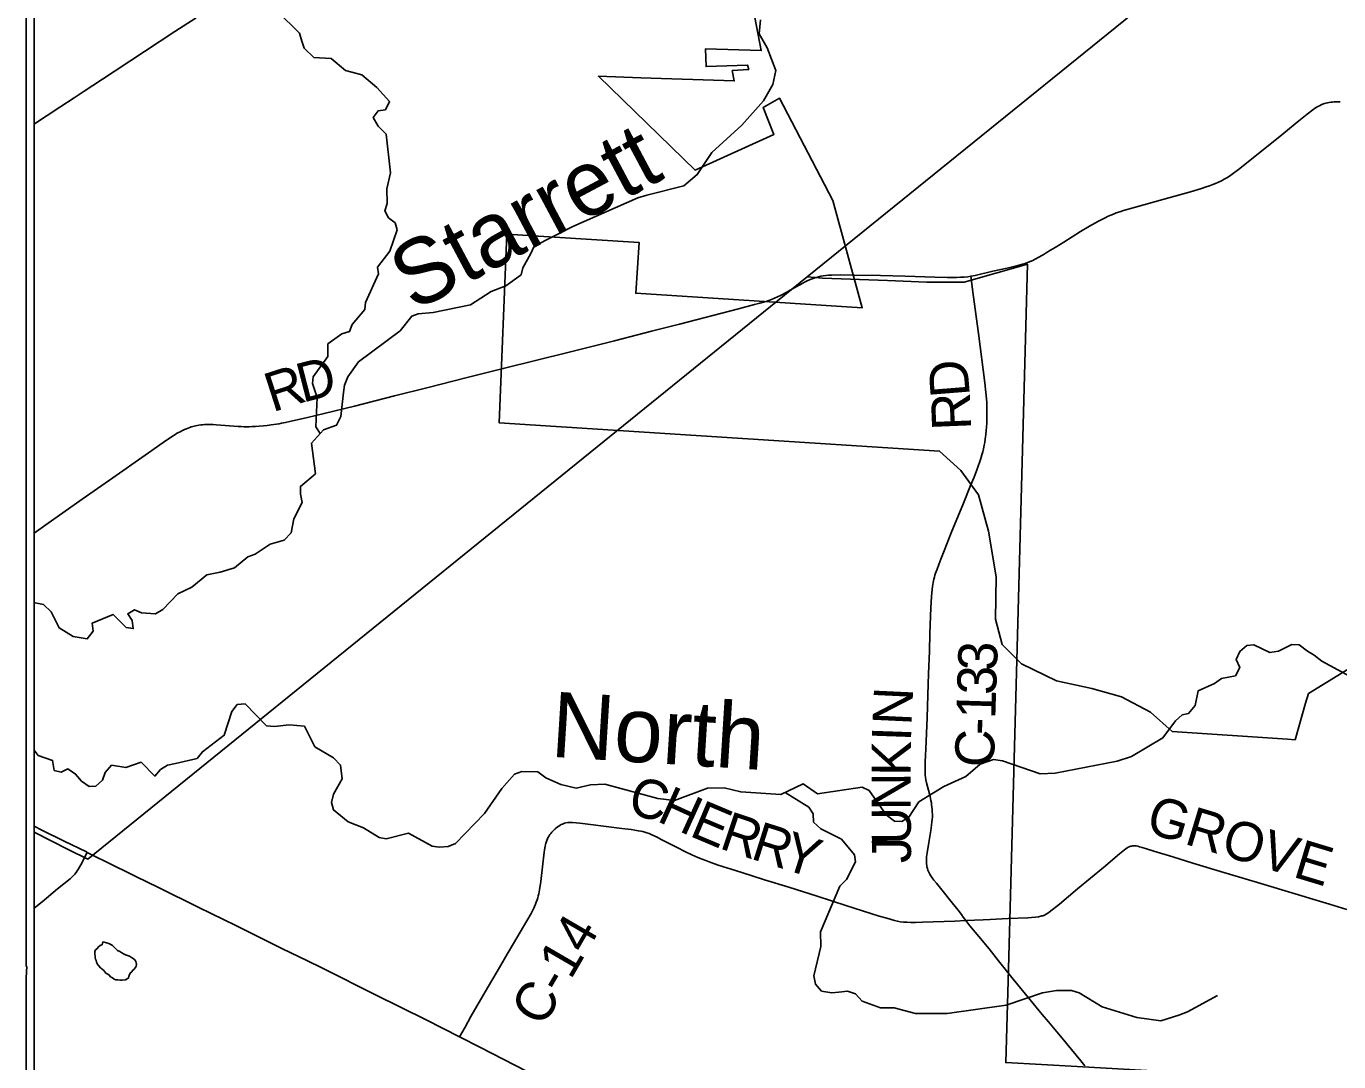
# Model space of a CAD drawing. Extents: x -5.4 to 49.9, y 13.2 to 48.4.
# Drawn here: x 26.266 to 28.171, y 44.845 to 46.348 of the extents above; entities that cross this region are included whole.
import ezdxf

# ---------------------------------------------------------------- set-up
doc = ezdxf.new("R2010")
doc.units = 0
for name, color, linetype in [('GM_X_Corporation', 7, 'Continuous'), ('GM_X_County_Road', 7, 'Continuous'), ('GM_X_County_Road_Text', 7, 'Continuous'), ('GM_X_Minor_Lake', 7, 'Continuous'), ('GM_X_Minor_River', 7, 'Continuous'), ('GM_X_Minor_River_Text', 7, 'Continuous'), ('GM_X_Township', 7, 'Continuous'), ('GM_X_Township_Road', 7, 'Continuous')]:
    doc.layers.add(name, color=color, linetype=linetype)

msp = doc.modelspace()

# ---------------------------------------------------------------- linework, layer by layer
at = {"layer": 'GM_X_Corporation'}
for p, q in [((26.2655, 46.6728), (26.2655, 44.9832)), ((26.2655, 44.9666), (26.2655, 44.8206))]:
    msp.add_line(p, q, dxfattribs=at)
for points in [[(28.3968, 45.5449), (28.1271, 45.3795), (28.123, 45.3654), (28.1079, 45.3123), (28.0969, 45.313), (27.9295, 45.3243), (27.898, 45.3524), (27.8556, 45.3746), (27.8126, 45.387), (27.7613, 45.3977), (27.7105, 45.4224), (27.6823, 45.4505), (27.6728, 45.4873), (27.674, 45.5489), (27.6626, 45.6154), (27.6481, 45.6682), (27.6227, 45.7031), (27.5916, 45.7316), (26.9521, 45.7726), (26.9634, 46.0466), (27.1552, 46.0345), (27.1505, 45.9606), (27.4794, 45.9397), (27.4366, 46.0951), (27.359, 46.2441), (27.3354, 46.2306), (27.3511, 46.191), (27.2369, 46.1395), (27.0962, 46.2758), (27.158, 46.2736), (27.2935, 46.2689), (27.2906, 46.284), (27.3145, 46.2856), (27.3129, 46.2919), (27.2526, 46.2898), (27.2517, 46.3155), (27.3326, 46.3129), (27.321, 46.3737)], [(26.2655, 44.9832), (26.2665, 44.9831), (26.2655, 44.9666)]]:
    msp.add_lwpolyline(points, dxfattribs=at)
at = {"layer": 'GM_X_County_Road'}
for points in [[(27.7269, 46.0083), (27.7294, 46.0095), (27.7316, 46.0107), (27.7336, 46.0119), (27.7418, 46.0164), (27.7466, 46.0192), (27.7529, 46.023), (27.7594, 46.027), (27.772, 46.0349), (27.7961, 46.0501), (27.8094, 46.0581), (27.8224, 46.0654), (27.8318, 46.0702), (27.8354, 46.0719), (27.8402, 46.074), (27.844, 46.0756), (27.8482, 46.0772), (27.8531, 46.0788), (27.8588, 46.0807), (27.8761, 46.0857), (27.9156, 46.0968), (27.9557, 46.108), (27.9718, 46.1128), (27.9787, 46.115), (27.9836, 46.1167), (27.9884, 46.1184), (27.9924, 46.1201), (27.9968, 46.122), (28.0009, 46.124), (28.005, 46.1261), (28.0086, 46.1283), (28.0126, 46.1309), (28.0164, 46.1335), (28.0254, 46.1402), (28.0831, 46.1864), (28.113, 46.2108), (28.1251, 46.2205), (28.1335, 46.2269), (28.136, 46.2287), (28.1386, 46.2303), (28.1408, 46.2317), (28.1434, 46.233), (28.1459, 46.2342), (28.1478, 46.235), (28.1503, 46.236), (28.1528, 46.2367), (28.1547, 46.2372), (28.1572, 46.2377), (28.1596, 46.238), (28.162, 46.2383), (28.1644, 46.2384), (28.1669, 46.2385), (28.1699, 46.2385), (28.1731, 46.2384)], [(27.6368, 45.9853), (27.6433, 45.9866), (27.6691, 45.9925), (27.6896, 45.9971), (27.6993, 45.9994), (27.7053, 46.0009), (27.7118, 46.0028), (27.7158, 46.0041), (27.7191, 46.0052), (27.7221, 46.0063), (27.7256, 46.0077), (27.7269, 46.0083)], [(27.3746, 45.965), (27.3783, 45.9671), (27.3929, 45.9753), (27.3964, 45.9771), (27.3996, 45.9787), (27.4026, 45.9801), (27.4054, 45.9812), (27.4083, 45.9823), (27.4119, 45.9835), (27.4157, 45.9845), (27.4192, 45.9853), (27.4228, 45.9859), (27.4267, 45.9864), (27.4303, 45.9868), (27.4334, 45.987)], [(27.4334, 45.987), (27.4348, 45.9871), (27.4472, 45.9874), (27.4678, 45.9871), (27.5057, 45.9862), (27.5417, 45.9854), (27.5845, 45.984), (27.6032, 45.9835), (27.61, 45.9834), (27.6164, 45.9835), (27.622, 45.9838), (27.6273, 45.9841), (27.6324, 45.9847), (27.6368, 45.9853)], [(27.6295, 45.0497), (27.6261, 45.0547), (27.6233, 45.0586), (27.6184, 45.0647), (27.6098, 45.0755), (27.5948, 45.0945), (27.587, 45.1043), (27.5835, 45.1086), (27.582, 45.1106), (27.5791, 45.1147), (27.5776, 45.1172), (27.5764, 45.1192), (27.5754, 45.1213), (27.5747, 45.1232), (27.5739, 45.1255), (27.5733, 45.1277), (27.573, 45.1299), (27.5726, 45.1324), (27.5725, 45.1349), (27.5725, 45.1375), (27.5726, 45.1399), (27.5728, 45.1422), (27.5736, 45.1483), (27.576, 45.163), (27.577, 45.1691), (27.579, 45.1807), (27.5801, 45.1885), (27.5806, 45.1932), (27.5809, 45.1968), (27.5811, 45.2002), (27.5811, 45.2036), (27.581, 45.2076), (27.5809, 45.211), (27.5805, 45.2147), (27.5801, 45.2178), (27.5797, 45.221), (27.5791, 45.224), (27.5785, 45.2272), (27.5778, 45.23), (27.5754, 45.2391), (27.5727, 45.2499), (27.5718, 45.254), (27.5711, 45.2578), (27.5708, 45.2611), (27.5705, 45.2641), (27.5705, 45.2705), (27.5708, 45.2802), (27.5711, 45.2895), (27.5715, 45.2994), (27.5734, 45.3441), (27.5747, 45.3777), (27.5756, 45.4081), (27.5769, 45.441), (27.5777, 45.4665), (27.5791, 45.5037), (27.5801, 45.5205), (27.5809, 45.5306), (27.5814, 45.5348), (27.5818, 45.5378), (27.5823, 45.5405), (27.5828, 45.543), (27.5833, 45.5454), (27.5841, 45.5482), (27.5849, 45.5511), (27.5859, 45.5542), (27.5879, 45.56), (27.5903, 45.5669), (27.5932, 45.5746), (27.5981, 45.5867), (27.6086, 45.6126), (27.6263, 45.6558), (27.6367, 45.6815), (27.6417, 45.6938), (27.6453, 45.703), (27.6503, 45.7164), (27.6517, 45.7209), (27.6532, 45.7259), (27.6544, 45.7306), (27.6555, 45.7349), (27.6565, 45.7399), (27.6572, 45.7441), (27.658, 45.7495), (27.6588, 45.7552), (27.6594, 45.7616), (27.6598, 45.7663), (27.6601, 45.7719), (27.6602, 45.7769), (27.6604, 45.7845), (27.6604, 45.7924), (27.6603, 45.7976), (27.6601, 45.8023), (27.659, 45.8166), (27.6575, 45.8308), (27.6482, 45.9023), (27.6405, 45.959), (27.6368, 45.9853)], [(26.2771, 45.6125), (26.294, 45.6243), (26.3468, 45.6615), (26.3865, 45.6892), (26.4429, 45.729), (26.4643, 45.7439), (26.4777, 45.753), (26.4812, 45.7552), (26.4837, 45.7568), (26.4867, 45.7585), (26.4889, 45.7596), (26.4912, 45.7609), (26.4934, 45.7619), (26.4954, 45.7629), (26.4981, 45.764), (26.5004, 45.7649), (26.5028, 45.7657), (26.5052, 45.7665), (26.5073, 45.7671), (26.5094, 45.7677), (26.5114, 45.7682), (26.5137, 45.7687), (26.5162, 45.7691), (26.5191, 45.7695), (26.5214, 45.7698), (26.5243, 45.77), (26.528, 45.7702), (26.5326, 45.7701), (26.5368, 45.77), (26.5413, 45.7698), (26.5542, 45.7688), (26.5734, 45.7672), (26.5774, 45.767), (26.5817, 45.7668), (26.5852, 45.7668), (26.589, 45.7668), (26.5934, 45.767), (26.5983, 45.7673), (26.6036, 45.7676), (26.6098, 45.7682), (26.6152, 45.7687), (26.6209, 45.7694), (26.6248, 45.7699), (26.6289, 45.7705), (26.6326, 45.7711), (26.6362, 45.7718), (26.6419, 45.7729), (26.6501, 45.7747), (26.6737, 45.7801), (26.6979, 45.7859), (26.7419, 45.7969), (26.8003, 45.8116), (26.8473, 45.8235), (26.9058, 45.8382), (26.9582, 45.8512), (27.054, 45.8752), (27.1197, 45.8917), (27.1733, 45.9054), (27.2142, 45.916), (27.2996, 45.938), (27.3231, 45.9441), (27.3304, 45.9461), (27.3362, 45.9478), (27.3397, 45.9489), (27.3435, 45.9502), (27.3474, 45.9516), (27.3517, 45.9534), (27.3561, 45.9553), (27.3608, 45.9575), (27.3696, 45.9622), (27.3746, 45.965)], [(26.2771, 45.1867), (26.2882, 45.1813), (26.3205, 45.1653), (26.3529, 45.1494), (26.354, 45.1488)], [(26.8947, 44.8808), (26.9027, 44.8952), (26.9112, 44.9104), (26.932, 44.9464), (26.9527, 44.9818), (26.9639, 45.0011), (26.9731, 45.0167), (26.9922, 45.0492), (26.9984, 45.0602), (27.0024, 45.0679), (27.0036, 45.0704), (27.0049, 45.0736), (27.006, 45.0764), (27.0073, 45.08), (27.0082, 45.0829), (27.009, 45.0859), (27.0097, 45.0886), (27.0102, 45.0913), (27.0109, 45.0944), (27.0128, 45.1067), (27.0152, 45.1277), (27.0175, 45.1489), (27.018, 45.1521), (27.0184, 45.1552), (27.0189, 45.1578), (27.0195, 45.1599), (27.0201, 45.1622), (27.0209, 45.1645), (27.0216, 45.1663), (27.0224, 45.1684), (27.0234, 45.1707), (27.0246, 45.173), (27.0258, 45.1748), (27.027, 45.1764), (27.0285, 45.1781), (27.03, 45.1798), (27.0333, 45.1829), (27.0369, 45.1858), (27.0387, 45.187), (27.0405, 45.1882), (27.0422, 45.1891), (27.044, 45.1899), (27.0453, 45.1905), (27.0472, 45.1911), (27.0491, 45.1916), (27.0517, 45.1921), (27.0541, 45.1924), (27.0563, 45.1923), (27.0586, 45.1922), (27.0691, 45.1912), (27.0849, 45.1892), (27.1073, 45.1864), (27.1302, 45.1836), (27.1436, 45.1819), (27.1491, 45.1811), (27.154, 45.1803), (27.1577, 45.1796), (27.1608, 45.179), (27.1636, 45.1782), (27.1667, 45.1772), (27.17, 45.176), (27.1736, 45.1745), (27.1815, 45.1708), (27.1876, 45.1677), (27.2108, 45.1557), (27.2219, 45.15), (27.2319, 45.1452), (27.2404, 45.1414), (27.2468, 45.1388), (27.252, 45.1368), (27.2572, 45.1349), (27.2702, 45.1304), (27.2891, 45.1243), (27.3045, 45.1194), (27.3376, 45.109), (27.3725, 45.0982), (27.4141, 45.0851), (27.4555, 45.0718), (27.5041, 45.0563), (27.5148, 45.0531), (27.526, 45.05), (27.5304, 45.0489), (27.5345, 45.0482), (27.5392, 45.0476), (27.5444, 45.0473), (27.5498, 45.0471), (27.5568, 45.0471), (27.5666, 45.0474), (27.614, 45.049), (27.6295, 45.0497)], [(26.2771, 45.0678), (26.2885, 45.0772), (26.311, 45.0958), (26.3293, 45.1106), (26.3322, 45.1133), (26.3342, 45.1153), (26.3361, 45.1173), (26.3378, 45.1194), (26.3395, 45.1218), (26.3416, 45.125), (26.3468, 45.1341), (26.3522, 45.1452), (26.354, 45.1488)], [(26.354, 45.1488), (26.3676, 45.1421)], [(27.6652, 45.0513), (27.691, 45.0527), (27.7196, 45.0539), (27.7249, 45.0543), (27.7308, 45.0548), (27.7351, 45.0554), (27.7386, 45.0561), (27.7403, 45.0565), (27.7417, 45.0569), (27.7429, 45.0573), (27.7441, 45.0579), (27.7464, 45.0592), (27.7488, 45.0607), (27.7507, 45.0621), (27.7655, 45.0738), (27.7917, 45.0957), (27.8295, 45.127), (27.8527, 45.1468), (27.86, 45.1525), (27.8621, 45.1541), (27.8641, 45.1554), (27.8655, 45.1562), (27.8668, 45.1569), (27.868, 45.1574), (27.8691, 45.1578), (27.8702, 45.158), (27.8715, 45.1582), (27.8727, 45.1584), (27.874, 45.1584), (27.8754, 45.1583), (27.8771, 45.1581), (27.8794, 45.1577), (27.8819, 45.1571), (27.8858, 45.1561), (27.8921, 45.1542), (27.9028, 45.1508), (27.9301, 45.1423), (27.9592, 45.1334), (27.9996, 45.121), (28.0306, 45.1118), (28.0627, 45.1021), (28.143, 45.078), (28.1579, 45.0735), (28.1829, 45.0659)], [(26.3676, 45.1421), (26.3796, 45.1361), (26.4258, 45.1133), (26.4565, 45.0982), (26.5161, 45.0688), (26.5696, 45.0425), (26.6376, 45.009), (26.6728, 44.9919), (26.6957, 44.9806), (26.7728, 44.9419), (26.8462, 44.9055), (26.8947, 44.8808)], [(27.6295, 45.0497), (27.655, 45.0508), (27.6652, 45.0513)], [(26.8947, 44.8808), (26.925, 44.8655), (27.009, 44.8225), (27.0663, 44.7925), (27.196, 44.7242), (27.2235, 44.7097), (27.2445, 44.6989), (27.2809, 44.68), (27.3256, 44.6569), (27.3583, 44.6402), (27.4753, 44.5798), (27.506, 44.5634), (27.543, 44.544)]]:
    msp.add_lwpolyline(points, dxfattribs=at)
at = {"layer": 'GM_X_Minor_Lake'}
msp.add_lwpolyline([(26.3766, 45.0189), (26.3785, 45.0185), (26.3819, 45.0173), (26.3854, 45.0165), (26.3884, 45.015), (26.3906, 45.0134), (26.3933, 45.0111), (26.3959, 45.0084), (26.3981, 45.0065), (26.4012, 45.005), (26.4042, 45.003), (26.4076, 45.0011), (26.4095, 45.0003), (26.4125, 44.9992), (26.4155, 44.998), (26.4182, 44.9964), (26.4208, 44.9945), (26.4234, 44.9926), (26.4245, 44.9903), (26.4253, 44.9884), (26.4256, 44.9861), (26.4252, 44.9838), (26.4241, 44.9816), (26.4218, 44.9789), (26.4199, 44.9774), (26.4187, 44.9755), (26.4168, 44.974), (26.4152, 44.9714), (26.4144, 44.9687), (26.414, 44.9665), (26.4121, 44.965), (26.4095, 44.9638), (26.4049, 44.9631), (26.4026, 44.9632), (26.3985, 44.9636), (26.3954, 44.964), (26.3932, 44.9648), (26.3909, 44.9667), (26.3879, 44.9682), (26.386, 44.9706), (26.3841, 44.9721), (26.3811, 44.9736), (26.3781, 44.9771), (26.3759, 44.9794), (26.3732, 44.9813), (26.3706, 44.9844), (26.3683, 44.9871), (26.3676, 44.9897), (26.3669, 44.992), (26.3661, 44.9939), (26.3658, 44.9958), (26.3654, 44.9985), (26.3651, 45.0004), (26.3651, 45.0023), (26.3651, 45.005), (26.3659, 45.0072), (26.3682, 45.0087), (26.3713, 45.0125), (26.3739, 45.014), (26.3758, 45.0147), (26.3766, 45.0189)], dxfattribs=at)
at = {"layer": 'GM_X_Minor_River'}
for points in [[(26.6921, 45.7569), (26.6862, 45.7665), (26.688, 45.8093), (26.6811, 45.8296), (26.682, 45.8391), (26.7033, 45.8687), (26.7036, 45.887), (26.7239, 45.9019), (26.7349, 45.9051), (26.7385, 45.9153), (26.757, 45.9371), (26.758, 45.9473), (26.7772, 45.9888), (26.7754, 45.9987), (26.7932, 46.022), (26.8043, 46.0526), (26.8014, 46.0629), (26.7917, 46.0702), (26.7862, 46.0802), (26.7897, 46.0908), (26.7889, 46.1121), (26.7946, 46.1355), (26.7883, 46.1918), (26.7763, 46.2034), (26.7693, 46.2157), (26.7763, 46.2254), (26.7869, 46.2272), (26.7928, 46.2392), (26.7745, 46.2596), (26.7528, 46.2778), (26.729, 46.2839), (26.708, 46.3017), (26.683, 46.3032), (26.6688, 46.3163), (26.6656, 46.3266), (26.6623, 46.3384), (26.6302, 46.3697)], [(26.2771, 45.5103), (26.2784, 45.511), (26.2905, 45.5089), (26.3017, 45.4981), (26.3135, 45.4747), (26.3338, 45.4623), (26.3542, 45.4589), (26.3627, 45.4702), (26.361, 45.4816), (26.3915, 45.4944), (26.4106, 45.4755), (26.4208, 45.4738), (26.4191, 45.4853), (26.4128, 45.4952), (26.4227, 45.5012), (26.4329, 45.4964), (26.453, 45.4954), (26.4637, 45.5017), (26.4857, 45.5241), (26.5059, 45.5341), (26.5278, 45.5516), (26.5472, 45.5559), (26.5681, 45.562), (26.5873, 45.578), (26.598, 45.5817), (26.6199, 45.5962), (26.64, 45.6023), (26.6504, 45.6128), (26.6542, 45.6329), (26.6659, 45.6566), (26.6638, 45.6688), (26.6636, 45.6802), (26.6855, 45.6985), (26.6797, 45.743), (26.6971, 45.7625), (26.7162, 45.769), (26.7224, 45.7815), (26.726, 45.8164), (26.7277, 45.827), (26.7324, 45.8394), (26.7479, 45.8609), (26.8085, 45.9063), (26.8252, 45.9273), (26.8347, 45.9309), (26.8563, 45.9329), (26.9107, 45.9438), (26.9406, 45.9631), (26.962, 45.9716), (26.9842, 45.9876), (26.9863, 45.9974), (26.9983, 46.0185), (27.003, 46.0291), (27.0592, 46.0574), (27.1535, 46.0993), (27.1665, 46.1029), (27.2205, 46.1165), (27.2397, 46.133), (27.2607, 46.1649), (27.3046, 46.2045), (27.3358, 46.2401), (27.3494, 46.2639), (27.3539, 46.2839), (27.3412, 46.3168), (27.3297, 46.3375), (27.3316, 46.3579)], [(26.8205, 45.1768), (26.8551, 45.158), (26.8649, 45.1564), (26.8782, 45.1573), (26.8889, 45.1617), (26.9309, 45.2051), (26.9561, 45.2416), (26.9746, 45.2622), (26.9853, 45.2662), (27.0084, 45.2658), (27.0197, 45.2573), (27.0415, 45.2475), (27.0642, 45.2422), (27.0847, 45.2468), (27.1056, 45.2477), (27.1826, 45.2271), (27.2065, 45.2241), (27.2545, 45.242), (27.2788, 45.2427), (27.303, 45.2367), (27.3609, 45.2331), (27.3934, 45.2482), (27.4144, 45.2338), (27.479, 45.2435), (27.4892, 45.2388), (27.5141, 45.2034), (27.5264, 45.1941), (27.537, 45.1936), (27.547, 45.1999), (27.5614, 45.2221), (27.5977, 45.2443), (27.6298, 45.259), (27.6506, 45.277), (27.67, 45.2835), (27.6829, 45.2818), (27.7379, 45.2631), (27.7592, 45.2639), (27.8493, 45.2812), (27.8703, 45.288), (27.9158, 45.3151), (27.934, 45.3399), (27.9436, 45.3485), (27.9532, 45.3506), (27.9628, 45.3619), (27.9673, 45.3834), (27.9906, 45.3941), (28.001, 45.4015), (28.0211, 45.4054), (28.0274, 45.4175), (28.0222, 45.429), (28.0277, 45.4407), (28.0377, 45.4492), (28.048, 45.4502), (28.0713, 45.4392), (28.0839, 45.4409), (28.1033, 45.4505), (28.1136, 45.4504), (28.1259, 45.4411), (28.1357, 45.4352), (28.1466, 45.4263), (28.1996, 45.3978)], [(26.2771, 45.2973), (26.283, 45.2895), (26.3037, 45.2823), (26.3061, 45.2678), (26.316, 45.2654), (26.3259, 45.2702), (26.3372, 45.2624), (26.3457, 45.2524), (26.357, 45.2443), (26.3665, 45.2449), (26.3761, 45.2535), (26.38, 45.2648), (26.3893, 45.2753), (26.4101, 45.2719), (26.4326, 45.2796), (26.4524, 45.2595), (26.4605, 45.2693), (26.4705, 45.2756), (26.4823, 45.2781), (26.5135, 45.2852), (26.5212, 45.2949), (26.553, 45.3188), (26.5642, 45.3532), (26.5719, 45.3633), (26.5833, 45.3646), (26.6143, 45.3326), (26.626, 45.3317), (26.6473, 45.334), (26.6693, 45.3322), (26.6844, 45.3023), (26.7114, 45.2863), (26.7219, 45.2755), (26.7242, 45.2558), (26.7114, 45.2335), (26.7085, 45.2214), (26.7114, 45.2104), (26.7331, 45.1933), (26.7554, 45.1846), (26.7779, 45.1706), (26.7881, 45.1686), (26.8205, 45.1768)], [(27.3672, 45.236), (27.402, 45.2143), (27.4083, 45.2047), (27.4085, 45.1929), (27.4193, 45.1832), (27.4494, 45.168), (27.468, 45.1453), (27.4694, 45.135), (27.4565, 45.1094), (27.4469, 45.1), (27.4189, 45.0336), (27.419, 45.012), (27.4092, 44.9696), (27.4113, 44.9574), (27.4203, 44.9474), (27.435, 44.9449), (27.4453, 44.9458), (27.4578, 44.9472), (27.4695, 44.9436), (27.4792, 44.9328), (27.5056, 44.9229), (27.5257, 44.923), (27.5567, 44.9149), (27.6025, 44.915), (27.6884, 44.927), (27.741, 44.9451), (27.7612, 44.9483), (27.7832, 44.9483), (27.7941, 44.9451), (27.8279, 44.9248), (27.8778, 44.9093), (27.9129, 44.9042), (27.9389, 44.9125), (27.9514, 44.9173), (27.995, 44.9409)]]:
    msp.add_lwpolyline(points, dxfattribs=at)
at = {"layer": 'GM_X_Township'}
msp.add_line((26.2771, 45.1783), (26.2771, 40.9761), dxfattribs=at)
for points in [[(28.0105, 47.4437), (26.2771, 47.4437), (26.2771, 45.1783)], [(26.2771, 45.1783), (26.3273, 45.1524), (26.3551, 45.1388), (27.3666, 45.9579), (27.3995, 45.9845), (28.089, 46.5424), (27.6308, 47.1161), (27.6499, 47.1327), (27.6877, 47.1657), (28.0105, 47.4437)], [(28.0105, 47.4437), (27.6877, 47.1657), (27.6499, 47.1327), (27.6308, 47.1161), (28.089, 46.5424), (27.3995, 45.9845), (27.4216, 45.9826), (27.5161, 45.979), (27.573, 45.9769), (27.6274, 45.9769), (27.7195, 46.0028), (27.6935, 45.0509), (27.691, 44.9621), (27.6878, 44.8437), (27.7914, 44.8377), (29.42, 44.7443), (29.8881, 44.7175), (31.3945, 44.5822), (32.3292, 44.4982), (33.0771, 44.431)], [(27.6878, 44.8437), (27.691, 44.9621), (27.6935, 45.0509), (27.7195, 46.0028), (27.6274, 45.9769), (27.573, 45.9769), (27.5161, 45.979), (27.4216, 45.9826), (27.3995, 45.9845), (27.3666, 45.9579), (26.3551, 45.1388), (26.3273, 45.1524), (26.2771, 45.1783)]]:
    msp.add_lwpolyline(points, dxfattribs=at)
at = {"layer": 'GM_X_Township_Road'}
for points in [[(26.2771, 46.2065), (26.2774, 46.2066), (26.3142, 46.2309), (26.3351, 46.2444), (26.3497, 46.2539), (26.3621, 46.2621), (26.3761, 46.2714), (26.3947, 46.2837), (26.4372, 46.3117), (26.4814, 46.3406), (26.512, 46.3608)], [(27.6635, 45.0086), (27.6634, 45.0087), (27.6485, 45.0268), (27.6357, 45.0422), (27.6295, 45.0497)], [(27.7968, 44.846), (27.7697, 44.879), (27.7619, 44.8883), (27.7499, 44.903), (27.7407, 44.9136), (27.7231, 44.9345), (27.6986, 44.9645), (27.6771, 44.9915), (27.6635, 45.0086)], [(27.8024, 44.8391), (27.7968, 44.846)]]:
    msp.add_lwpolyline(points, dxfattribs=at)

# ---------------------------------------------------------------- texts
at = {"layer": 'GM_X_County_Road_Text'}
for s, height, rotation, p in [('R', 0.0568, 17.8462, (26.623, 45.7876)), ('D', 0.0568, 14.4276, (26.6666, 45.8016)), ('D', 0.0568, 94.5522, (27.6357, 45.8117)), ('R', 0.0568, 92.3112, (27.6377, 45.7627)), ('3', 0.0568, 87.8294, (27.6747, 45.4118)), ('3', 0.0568, 88.1836, (27.6736, 45.3769)), ('N', 0.0568, 87.3289, (27.5508, 45.3325)), ('1', 0.0568, 88.2564, (27.6725, 45.3419)), ('-', 0.0568, 88.2591, (27.6718, 45.3186)), ('I', 0.0568, 87.9936, (27.55, 45.3093)), ('C', 0.0568, 88.2746, (27.6704, 45.2719)), ('K', 0.0568, 89.5811, (27.5496, 45.2597)), ('C', 0.0568, 345.4497, (27.1368, 45.2057)), ('H', 0.0568, 335.462, (27.1795, 45.1949)), ('N', 0.0568, 90.2659, (27.5498, 45.2099)), ('E', 0.0568, 337.168, (27.2267, 45.1734)), ('GROVE', 0.05682, 343.1312, (27.8888, 45.1788)), ('R', 0.0568, 341.5025, (27.2702, 45.1552)), ('U', 0.0568, 90.2842, (27.5501, 45.1599)), ('R', 0.0568, 342.534, (27.3156, 45.1401)), ('Y', 0.0568, 342.5293, (27.3601, 45.1261)), ('J', 0.0568, 90.2869, (27.5502, 45.1333)), ('C-14', 0.05682, 59.8438, (27.0157, 44.8934))]:
    msp.add_text(s, height=height, rotation=rotation, dxfattribs=at).set_placement(p)
at = {"layer": 'GM_X_Minor_River_Text'}
for s, height, rotation, p in [('Starrett', 0.09471, 28.0573, (26.8278, 45.9331)), ('North', 0.09469, 356.4149, (27.0257, 45.2878))]:
    msp.add_text(s, height=height, rotation=rotation, dxfattribs=at).set_placement(p)

doc.saveas('drawing.dxf')
